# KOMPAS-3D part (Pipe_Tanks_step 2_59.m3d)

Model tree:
1. X Axis
2. Y Axis
3. Z Axis  (labels: Pipe Dn 50; Valve Dy 50)
     Òîëùèíà ñòåíêè 1 = 1

Referenced files in C:\Documents and Settings\kashirsky\Мои документы\Camtasia Studio\Pipelines3D\Tanks\: Tanks_step 2.a3d
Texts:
  Pipe Dn 50
  Steel ASTM A295
  Three Point Plane
  Plane at Angle
  Line and Point Plane
  Axis through Two Vertices
  Axis of Feature
  Axis of Conical Surface
  Axis through Edge
  Trim by Surface
  Trim by Sketch
  Feature with No History
  Intersection Axis of Two Planes
  Two Line Plane
  Line and Face Plane
  Bend by line
  Hole in sheet body
  Cut in sheet body
  Point in CM
  Linear Dimension from Line to Point
  Surface Finish Symbol
  Geometric Tolerance Symbol
  Leader #1
  Leader #2
  Leader #3
  Shape Deviations and Datum
  Node point number
  Mark of coordination axis
  Node point designation
  Mark/Reference designation with leader
  Mark/reference designation on line
  Mark/Reference designation without leader
  Valve Dy 50
  Plane of section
